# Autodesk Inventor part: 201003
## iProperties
Created: 2007-12
Part Number: 201003
Document SubType Name: Modeling
Designer: MM
Density: 7.85 g/cm^3
Material: Steel
Description: SIDE MOUNTING BAR
Mass: 75.8289 g
Surface Area: 77.6706 cm^2
Volume: 9.65974 cm^3
Component Category: Lower Component
Author: MM
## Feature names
1. Sweep1
